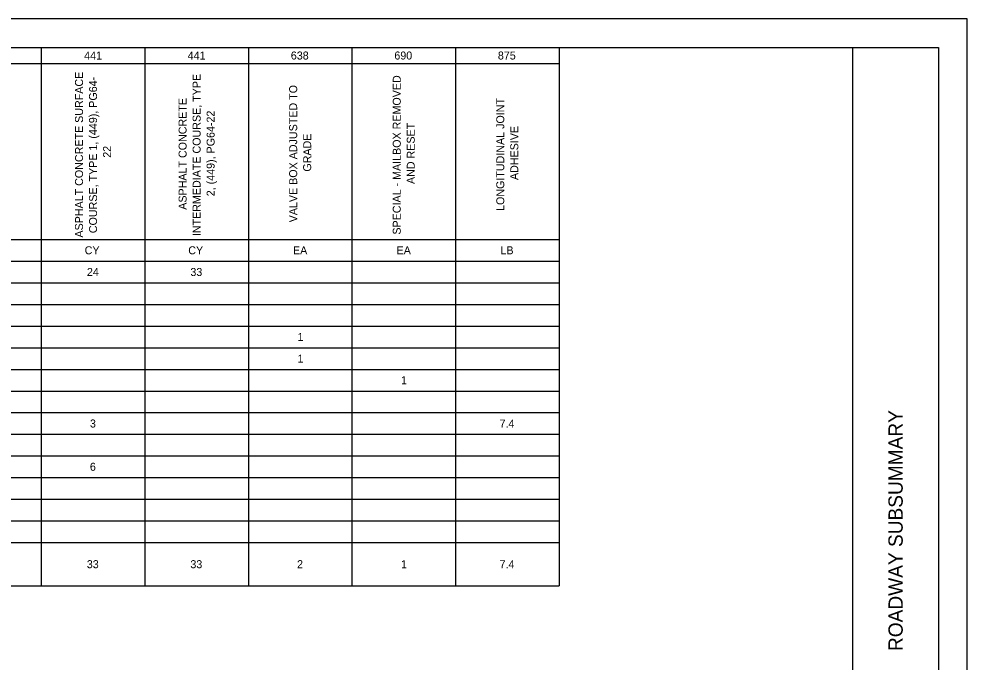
# Model space of a CAD drawing. Extents: x 0 to 34, y 0 to 22.
# Drawn here: x 17.42 to 34, y 10.75 to 22 of the extents above; entities that cross this region are included whole.
import ezdxf

# ---------------------------------------------------------------- set-up
doc = ezdxf.new("R2010")
doc.units = 0
for name, color, linetype in [('SH_Border', 7, 'Continuous'), ('SH_Cut_Line', 7, 'Continuous'), ('SH_Data', 7, 'Continuous'), ('SH_Text', 7, 'Continuous')]:
    doc.layers.add(name, color=color, linetype=linetype)

msp = doc.modelspace()

# ---------------------------------------------------------------- linework, layer by layer
at = {"layer": 'SH_Border'}
msp.add_line((32, 0.5), (32, 21.5), dxfattribs=at)
msp.add_lwpolyline([(1.5, 21.5), (33.5, 21.5), (33.5, 0.5), (1.5, 0.5)], close=True, dxfattribs=at)
at = {"layer": 'SH_Cut_Line'}
msp.add_lwpolyline([(0, 0), (34, 0), (34, 22), (0, 22)], close=True, dxfattribs=at)
at = {"layer": 'SH_Text'}
for p, q in [((1.5, 21.5), (26.864, 21.5)), ((17.805, 21.5), (17.805, 12.079)), ((19.617, 21.5), (19.617, 12.079)), ((21.429, 21.5), (21.429, 12.079)), ((23.24, 21.5), (23.24, 12.079)), ((25.052, 21.5), (25.052, 12.079)), ((26.864, 21.5), (26.864, 12.079)), ((8.747, 21.22), (26.864, 21.22)), ((8.747, 18.14), (26.864, 18.14)), ((1.5, 17.761), (26.864, 17.761)), ((1.5, 17.383), (26.864, 17.383)), ((1.5, 17.004), (26.864, 17.004)), ((1.5, 16.625), (26.864, 16.625)), ((1.5, 16.246), (26.864, 16.246)), ((1.5, 15.867), (26.864, 15.867)), ((1.5, 15.488), (26.864, 15.488)), ((1.5, 15.11), (26.864, 15.11)), ((1.5, 14.731), (26.864, 14.731)), ((1.5, 14.352), (26.864, 14.352)), ((1.5, 13.973), (26.864, 13.973)), ((1.5, 13.594), (26.864, 13.594)), ((1.5, 13.216), (26.864, 13.216)), ((1.5, 12.837), (26.864, 12.837)), ((1.5, 12.079), (26.864, 12.079))]:
    msp.add_line(p, q, dxfattribs=at)

# ---------------------------------------------------------------- texts
at = {"layer": 'SH_Data'}
msp.add_text('ROADWAY SUBSUMMARY', height=0.25, rotation=90, dxfattribs=at).set_placement((32.875, 10.938))
at = {"layer": 'SH_Text'}
for s, p in [('441', (18.556, 21.29)), ('441', (20.367, 21.29)), ('638', (22.171, 21.29)), ('690', (23.982, 21.29)), ('875', (25.793, 21.29)), ('CY', (18.565, 17.881)), ('CY', (20.377, 17.881)), ('EA', (22.209, 17.881)), ('EA', (24.021, 17.881)), ('LB', (25.838, 17.881)), ('24', (18.604, 17.502)), ('33', (20.414, 17.502)), ('1', (22.288, 16.365)), ('1', (22.288, 15.987)), ('1', (24.099, 15.608)), ('3', (18.657, 14.85)), ('7.4', (25.823, 14.85)), ('6', (18.656, 14.093)), ('33', (18.602, 12.388)), ('33', (20.414, 12.388)), ('2', (22.28, 12.388)), ('1', (24.099, 12.388)), ('7.4', (25.823, 12.388))]:
    msp.add_text(s, height=0.14, dxfattribs=at).set_placement(p)
for s, p in [('ASPHALT CONCRETE SURFACE ', (18.536, 18.174)), ('COURSE, TYPE 1, (449), PG64-', (18.781, 18.251)), ('INTERMEDIATE COURSE, TYPE ', (20.593, 18.199)), ('SPECIAL - MAILBOX REMOVED ', (24.094, 18.226)), ('VALVE BOX ADJUSTED TO ', (22.282, 18.441)), ('ASPHALT CONCRETE ', (20.348, 18.661)), ('LONGITUDINAL JOINT ', (25.905, 18.64)), ('2, (449), PG64-22', (20.838, 18.897)), ('AND RESET', (24.339, 19.111)), ('ADHESIVE', (26.15, 19.181)), ('GRADE', (22.527, 19.328)), ('22', (19.026, 19.571))]:
    msp.add_text(s, height=0.14, rotation=90, dxfattribs=at).set_placement(p)

doc.saveas('drawing.dxf')
